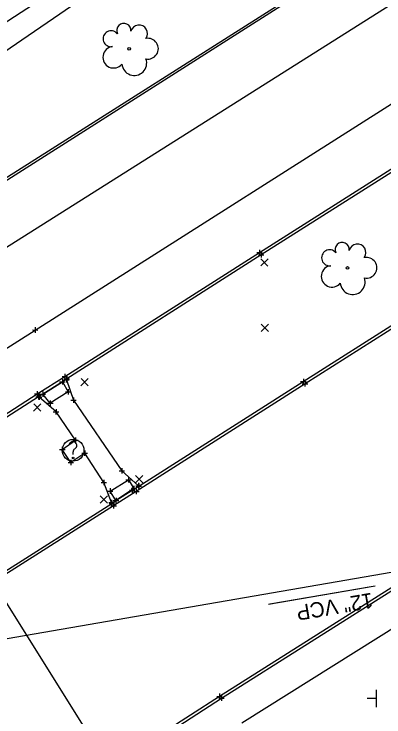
# Model space of a CAD drawing. Extents: x 142461 to 147261, y 511126 to 514697.
# Drawn here: x 145052.6 to 145120.6, y 512979.9 to 513109.1 of the extents above; entities that cross this region are included whole.
import ezdxf

# ---------------------------------------------------------------- set-up
doc = ezdxf.new("R2010")
doc.units = 0
for name, color, linetype in [('DR_X_Storm_Sewer', 7, 'Continuous'), ('DR_X_Text', 7, 'Continuous'), ('PM_X_Surveyed_Line', 7, 'Continuous'), ('PV_X_Curb', 7, 'Continuous'), ('PV_X_EOP', 7, 'Continuous'), ('PV_X_Walk', 7, 'Continuous'), ('RD_X_Concrete_Pad', 7, 'Continuous'), ('RD_X_Misc_Items', 7, 'Continuous'), ('SN_X_Public', 7, 'Continuous'), ('SV_X_Random_Point', 7, 'Continuous'), ('SV_X_Shot_Marker', 7, 'Continuous'), ('SV_X_Toe_of_Slope', 7, 'Continuous'), ('UT_X_Sanitary_Line', 7, 'Continuous'), ('VG_X_Cells', 7, 'Continuous')]:
    doc.layers.add(name, color=color, linetype=linetype)

msp = doc.modelspace()

# ---------------------------------------------------------------- linework, layer by layer
at = {"layer": 'DR_X_Storm_Sewer'}
for p, q in [((145313.55, 513281.39), (144904.71, 513002.46)), ((145191.29, 513018.34), (145030.57, 512990.68))]:
    msp.add_line(p, q, dxfattribs=at)
at = {"layer": 'DR_X_Text'}
for p, q in [((145099.62, 513000.63), (145118.94, 513003.96)), ((145099.62, 513000.63), (145118.94, 513003.96)), ((145099.38, 513000.6), (145117.17, 513003.66)), ((145100.33, 513000.76), (145118.23, 513003.84))]:
    msp.add_line(p, q, dxfattribs=at)
at = {"layer": 'PM_X_Surveyed_Line'}
for points in [[(144161.19, 512623.62), (144234.91, 512664.76), (144308.58, 512704.75), (144382.31, 512742.08), (144431.43, 512764.26), (144460.46, 512777.08), (144499.91, 512794.34), (144547.7, 512814.68), (144592.59, 512833.3), (144667.23, 512864.35), (144709.98, 512882.09), (144731.76, 512891.11), (144777.76, 512910.35), (144847.49, 512940.98), (144877.97, 512956.57), (144906.17, 512973.31), (144970.66, 513014.86), (145008.54, 513039.23), (145047.45, 513063.87), (145126.17, 513113.66), (145208.14, 513166.05), (145269.39, 513204.92)], [(144979.87, 513002.18), (145015.44, 513024.96), (145056.46, 513050.99), (145134.2, 513100.33), (145217.05, 513153.1), (145277.89, 513191.73), (145294.07, 513201.96)]]:
    msp.add_lwpolyline(points, dxfattribs=at)
at = {"layer": 'PV_X_Curb'}
for p, q in [((145133.14, 513087.09), (145098, 513064.8)), ((145105.75, 513041.54), (145145.07, 513066.52)), ((145098, 513064.8), (145062.26, 513042.04)), ((145061.46, 513041.49), (145057.86, 513039.2)), ((145062.26, 513042.04), (145061.46, 513041.49)), ((145075.53, 513022.29), (145105.75, 513041.54)), ((145057.86, 513039.2), (145057.05, 513038.71)), ((145057.05, 513038.71), (144988.2, 512994.75)), ((145074.28, 513021.55), (145075.53, 513022.29)), ((145071.31, 513019.66), (145074.28, 513021.55)), ((145070.55, 513019.1), (145071.31, 513019.66)), ((145038.09, 512998.53), (145070.55, 513019.1)), ((145090.73, 512983.33), (145125.57, 513005.34)), ((145064.23, 512966.25), (145090.73, 512983.33))]:
    msp.add_line(p, q, dxfattribs=at)
msp.add_lwpolyline([(144906.62, 512975.04), (144910.56, 512977.96), (144915.88, 512983.2), (144920.32, 512988.51), (144935.68, 513005.16), (144948.67, 513014.13), (144965.59, 513024.78), (145041.73, 513073.1), (145115.39, 513119.87), (145203.02, 513175.49), (145259.95, 513211.93), (145276.5, 513223.26), (145307.25, 513248.71)], dxfattribs=at)
at = {"layer": 'PV_X_EOP'}
for p, q in [((145097.71, 513065.24), (145132.83, 513087.57)), ((145145.45, 513066.05), (145106.07, 513041.1)), ((145061.9, 513042.47), (145097.71, 513065.24)), ((145056.84, 513039.25), (145061.9, 513042.47)), ((145106.07, 513041.1), (145075.05, 513021.32)), ((145021.77, 513016.73), (145056.84, 513039.25)), ((145075.05, 513021.32), (145070.88, 513018.67)), ((145070.88, 513018.67), (145038.29, 512998.03)), ((145125.29, 513005.73), (145090.36, 512983.65)), ((145090.36, 512983.65), (145064.01, 512966.73))]:
    msp.add_line(p, q, dxfattribs=at)
msp.add_lwpolyline([(145308.5, 513249.32), (145276.87, 513222.85), (145260.3, 513211.35), (145203.28, 513174.99), (145115.75, 513119.59), (145041.93, 513072.6), (144965.91, 513024.3), (144949.02, 513013.46), (144936.1, 513004.72), (144920.88, 512988.16), (144917.39, 512983.57), (144918.93, 512982.03), (144917.24, 512980.52), (144915.69, 512981.95)], dxfattribs=at)
at = {"layer": 'PV_X_Walk'}
msp.add_line((145126.2, 512998.67), (145094.47, 512978.71), dxfattribs=at)
for points in [[(145062.21, 513041.85), (145063.51, 513038.09), (145072.41, 513025.09), (145075.47, 513022.38)], [(145070.52, 513019.28), (145069.07, 513022.96), (145065.56, 513028.37), (145063.03, 513026.66), (145061.45, 513029.04), (145063.88, 513030.75), (145060.29, 513035.95), (145057.2, 513038.67)]]:
    msp.add_lwpolyline(points, dxfattribs=at)
at = {"layer": 'RD_X_Concrete_Pad'}
for points in [[(145061.46, 513041.49), (145062.51, 513039.64), (145059.24, 513037.56), (145057.86, 513039.2)], [(145071.31, 513019.66), (145070.25, 513021.4), (145073.62, 513023.45), (145074.59, 513021.84)]]:
    msp.add_lwpolyline(points, close=True, dxfattribs=at)
at = {"layer": 'RD_X_Misc_Items'}
msp.add_line((145063.42, 513028.12), (145063.43, 513028.6), dxfattribs=at)
for centre, radius in [((145063.43, 513028.88), 2), ((145063.42, 513027.47), 0.17)]:
    msp.add_circle(centre, radius, dxfattribs=at)
for centre, radius, start, end in [((145063.38, 513029.69), 0.754, 87.7326, 151.9471), ((145063.43, 513029.76), 0.688, 291.3416, 91.867), ((145064.01, 513028.63), 0.587, 124.8704, 183.4915)]:
    msp.add_arc(centre, radius, start, end, dxfattribs=at)
at = {"layer": 'SN_X_Public'}
for p, q in [((145119.12, 512984.87), (145119.12, 512981.67)), ((145119.12, 512983.27), (145117.52, 512983.27)), ((145119.12, 512983.27), (145119.12, 512983.27))]:
    msp.add_line(p, q, dxfattribs=at)
at = {"layer": 'SV_X_Random_Point'}
for p, q in [((145097.92, 513062.77), (145099.27, 513064.09)), ((145097.94, 513064.1), (145099.26, 513062.75)), ((145097.99, 513050.73), (145099.33, 513052.07)), ((145097.99, 513052.07), (145099.33, 513050.73)), ((145064.88, 513040.74), (145066.23, 513042.06)), ((145064.9, 513042.07), (145066.21, 513040.72)), ((145056.18, 513036.1), (145057.52, 513037.42)), ((145056.19, 513037.43), (145057.51, 513036.08)), ((145074.9, 513022.91), (145076.25, 513024.23)), ((145074.91, 513024.24), (145076.23, 513022.89)), ((145068.4, 513019.18), (145069.75, 513020.5)), ((145068.41, 513020.51), (145069.73, 513019.16))]:
    msp.add_line(p, q, dxfattribs=at)
at = {"layer": 'SV_X_Shot_Marker'}
for p, q in [((145097.21, 513065.24), (145098.21, 513065.23)), ((145097.5, 513064.8), (145098.5, 513064.79)), ((145097.71, 513065.74), (145097.7, 513064.74)), ((145097.71, 513065.24), (145097.71, 513065.24)), ((145098, 513065.3), (145097.99, 513064.3)), ((145098, 513064.8), (145098, 513064.8)), ((145055.96, 513051), (145056.96, 513050.99)), ((145056.46, 513051.49), (145056.45, 513050.49)), ((145056.46, 513050.99), (145056.46, 513050.99)), ((145061.91, 513042.97), (145061.9, 513041.97)), ((145060.96, 513041.49), (145061.96, 513041.48)), ((145061.4, 513042.48), (145062.4, 513042.47)), ((145061.47, 513041.99), (145061.46, 513040.99)), ((145061.46, 513041.49), (145061.46, 513041.49)), ((145061.71, 513041.85), (145062.71, 513041.84)), ((145061.76, 513042.05), (145062.76, 513042.04)), ((145061.9, 513042.47), (145061.9, 513042.47)), ((145062.21, 513042.35), (145062.2, 513041.35)), ((145062.21, 513041.85), (145062.21, 513041.85)), ((145062.27, 513042.54), (145062.25, 513041.54)), ((145062.26, 513042.04), (145062.26, 513042.04)), ((145105.25, 513041.55), (145106.25, 513041.54)), ((145105.76, 513042.04), (145105.75, 513041.04)), ((145105.75, 513041.54), (145105.75, 513041.54)), ((145106.07, 513041.6), (145106.06, 513040.6)), ((145062.51, 513040.14), (145062.51, 513039.14)), ((145105.57, 513041.1), (145106.57, 513041.09)), ((145106.07, 513041.1), (145106.07, 513041.1)), ((145056.34, 513039.26), (145057.34, 513039.25)), ((145056.85, 513039.75), (145056.84, 513038.75)), ((145056.84, 513039.25), (145056.84, 513039.25)), ((145057.05, 513039.21), (145057.04, 513038.22)), ((145057.21, 513039.17), (145057.2, 513038.17)), ((145057.36, 513039.21), (145058.36, 513039.2)), ((145057.86, 513039.7), (145057.85, 513038.7)), ((145057.86, 513039.2), (145057.86, 513039.2)), ((145062.01, 513039.64), (145063.01, 513039.64)), ((145062.51, 513039.64), (145062.51, 513039.64)), ((145056.55, 513038.72), (145057.55, 513038.71)), ((145056.7, 513038.68), (145057.7, 513038.67)), ((145057.05, 513038.71), (145057.05, 513038.71)), ((145057.2, 513038.67), (145057.2, 513038.67)), ((145058.74, 513037.56), (145059.74, 513037.56)), ((145059.24, 513038.06), (145059.24, 513037.06)), ((145059.24, 513037.56), (145059.24, 513037.56)), ((145063.01, 513038.1), (145064.01, 513038.09)), ((145063.52, 513038.59), (145063.51, 513037.59)), ((145063.51, 513038.09), (145063.51, 513038.09)), ((145060.29, 513036.45), (145060.28, 513035.45)), ((145059.79, 513035.96), (145060.79, 513035.95)), ((145060.29, 513035.95), (145060.29, 513035.95)), ((145063.88, 513031.25), (145063.87, 513030.25)), ((145063.38, 513030.76), (145064.38, 513030.75)), ((145063.88, 513030.75), (145063.88, 513030.75)), ((145060.95, 513029.04), (145061.95, 513029.03)), ((145061.45, 513029.54), (145061.44, 513028.54)), ((145061.45, 513029.04), (145061.45, 513029.04)), ((145065.56, 513028.87), (145065.55, 513027.87)), ((145063.03, 513027.16), (145063.02, 513026.16)), ((145065.06, 513028.37), (145066.06, 513028.36)), ((145065.56, 513028.37), (145065.56, 513028.37)), ((145062.53, 513026.67), (145063.53, 513026.66)), ((145063.03, 513026.66), (145063.03, 513026.66)), ((145071.91, 513025.09), (145072.91, 513025.08)), ((145072.42, 513025.59), (145072.41, 513024.59)), ((145072.41, 513025.09), (145072.41, 513025.09)), ((145069.07, 513023.46), (145069.06, 513022.46)), ((145073.12, 513023.45), (145074.12, 513023.45)), ((145073.62, 513023.95), (145073.62, 513022.95)), ((145073.62, 513023.45), (145073.62, 513023.45)), ((145068.57, 513022.97), (145069.57, 513022.96)), ((145069.07, 513022.96), (145069.07, 513022.96)), ((145074.28, 513022.05), (145074.27, 513021.05)), ((145074.6, 513022.34), (145074.59, 513021.34)), ((145074.97, 513022.38), (145075.97, 513022.37)), ((145075.03, 513022.3), (145076.03, 513022.29)), ((145075.47, 513022.88), (145075.46, 513021.88)), ((145075.47, 513022.38), (145075.47, 513022.38)), ((145075.53, 513022.79), (145075.52, 513021.79)), ((145075.53, 513022.29), (145075.53, 513022.29)), ((145069.75, 513021.4), (145070.75, 513021.4)), ((145070.25, 513021.9), (145070.25, 513020.9)), ((145070.25, 513021.4), (145070.25, 513021.4)), ((145073.78, 513021.55), (145074.78, 513021.54)), ((145074.09, 513021.84), (145075.09, 513021.83)), ((145074.28, 513021.55), (145074.28, 513021.55)), ((145074.55, 513021.33), (145075.55, 513021.32)), ((145074.59, 513021.84), (145074.59, 513021.84)), ((145075.05, 513021.82), (145075.04, 513020.82)), ((145075.05, 513021.32), (145075.05, 513021.32)), ((145070.52, 513019.78), (145070.51, 513018.78)), ((145070.55, 513019.6), (145070.54, 513018.6)), ((145070.81, 513019.67), (145071.81, 513019.66)), ((145071.32, 513020.16), (145071.31, 513019.16)), ((145071.31, 513019.66), (145071.31, 513019.66)), ((145070.02, 513019.29), (145071.02, 513019.28)), ((145070.05, 513019.11), (145071.05, 513019.1)), ((145070.38, 513018.68), (145071.38, 513018.67)), ((145070.52, 513019.28), (145070.52, 513019.28)), ((145070.55, 513019.1), (145070.55, 513019.1)), ((145070.88, 513019.17), (145070.87, 513018.17)), ((145070.88, 513018.67), (145070.88, 513018.67)), ((145089.86, 512983.65), (145090.86, 512983.64)), ((145090.23, 512983.34), (145091.23, 512983.33)), ((145090.37, 512984.15), (145090.36, 512983.15)), ((145090.36, 512983.65), (145090.36, 512983.65)), ((145090.73, 512983.83), (145090.72, 512982.83)), ((145090.73, 512983.33), (145090.73, 512983.33))]:
    msp.add_line(p, q, dxfattribs=at)
at = {"layer": 'SV_X_Toe_of_Slope'}
msp.add_lwpolyline([(145536.33, 513468.51), (145487.34, 513431.87), (145445.96, 513398.71), (145400.54, 513359.53), (145354.59, 513321.64), (145305.79, 513280.24), (145266.24, 513246.77), (145228.58, 513220.65), (145175.08, 513189.66), (145126.31, 513155.94), (145081.98, 513127.67), (145034.97, 513097.1), (144983.36, 513063.49), (144934.41, 513028.84), (144889.77, 512994.77), (144833.63, 512962.42), (144772.97, 512934.59), (144716.73, 512910.04), (144663.56, 512886.77), (144614.86, 512866.63), (144547.92, 512838.93)], dxfattribs=at)
at = {"layer": 'UT_X_Sanitary_Line'}
msp.add_line((144979.11, 513115.64), (145082.93, 512950.11), dxfattribs=at)
at = {"layer": 'VG_X_Cells'}
for centre in [(145073.73, 513102.68), (145113.89, 513062.41)]:
    msp.add_circle(centre, 0.24, dxfattribs=at)
for centre, radius, start, end in [((145072.75, 513106.05), 1.32, 354.0047, 205.9741), ((145070.42, 513104.54), 1.47, 39.0625, 279.5412), ((145075.56, 513105.51), 1.55, 323.83, 165.0376), ((145077.19, 513102.71), 1.91, 259.1453, 101.4596), ((145070.88, 513101.13), 1.97, 96.1722, 320.5737), ((145074.68, 513100.07), 2.28, 184.9476, 19.4572), ((145112.9, 513065.77), 1.32, 354.0047, 205.9741), ((145115.71, 513065.24), 1.55, 323.83, 165.0376), ((145110.58, 513064.27), 1.47, 39.0625, 279.5412), ((145117.35, 513062.44), 1.91, 259.1453, 101.4596), ((145111.03, 513060.86), 1.97, 96.1722, 320.5737), ((145114.83, 513059.8), 2.28, 184.9476, 19.4572)]:
    msp.add_arc(centre, radius, start, end, dxfattribs=at)

# ---------------------------------------------------------------- texts
at = {"layer": 'DR_X_Text'}
msp.add_text('12" VCP', height=2.8, rotation=189.7645, dxfattribs=at).set_placement((145118.31, 513002.73))

doc.saveas('drawing.dxf')
